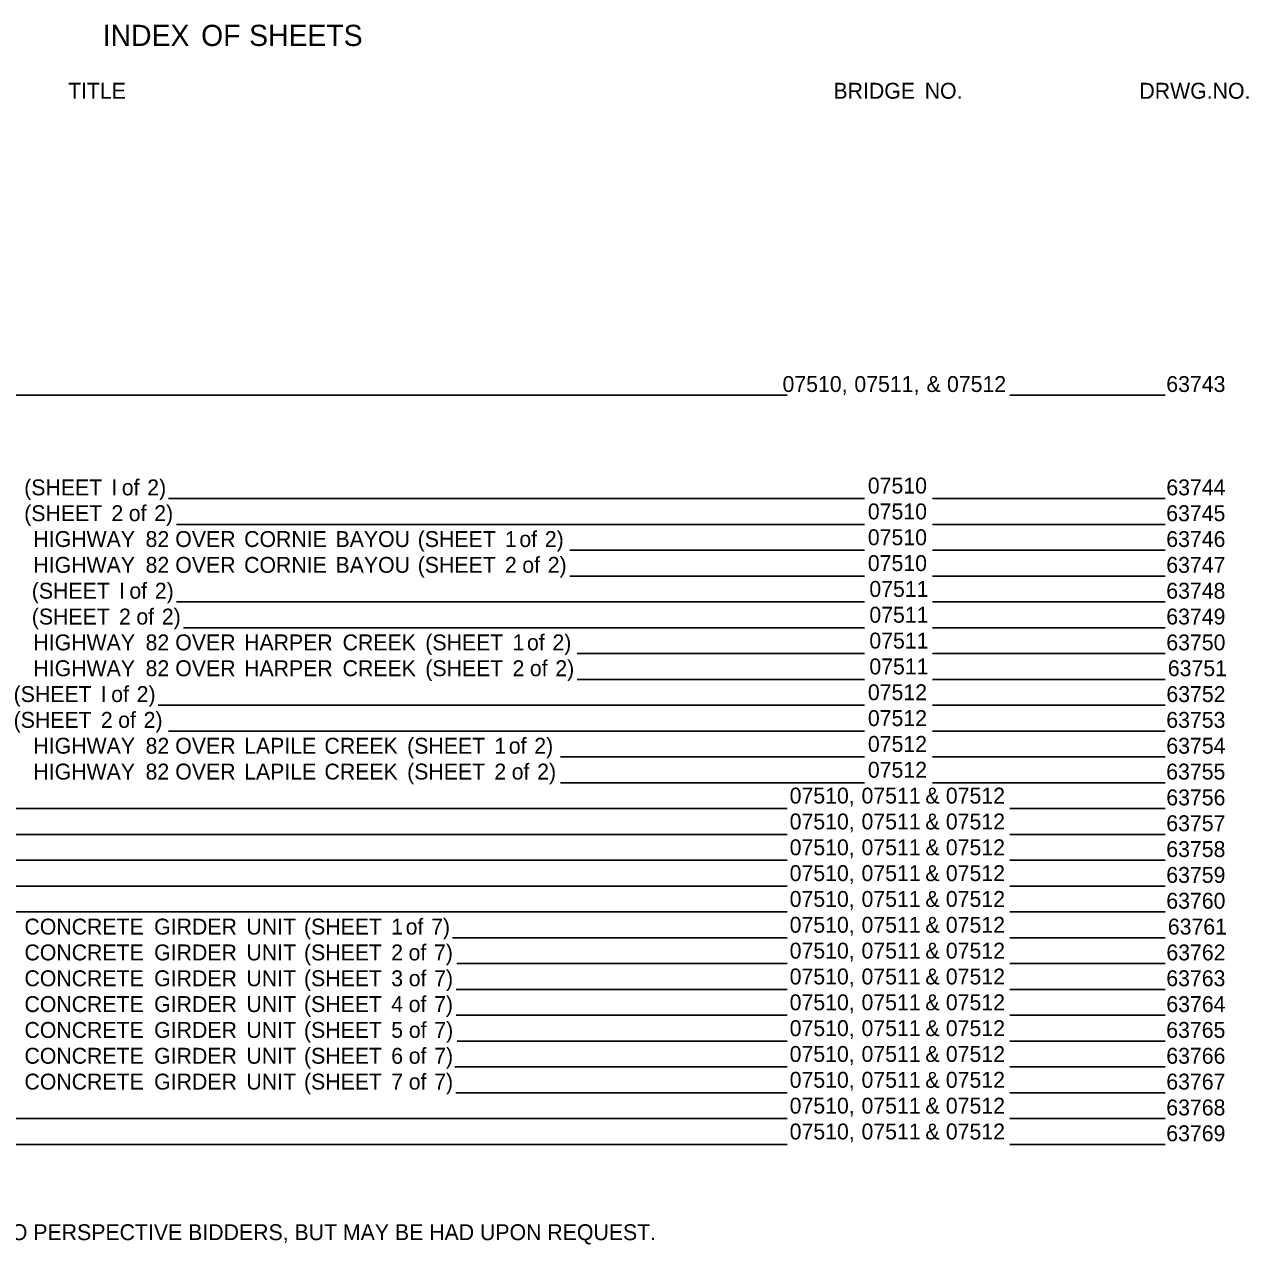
# Model space of a CAD drawing. Extents: x -1392 to 1630, y -1031 to 935.
# Drawn here: x -779 to 144, y -232 to 689 of the extents above; entities that cross this region are included whole.
import ezdxf

# ---------------------------------------------------------------- set-up
doc = ezdxf.new("R2010")
doc.units = 0
doc.layers.add('Default', color=7, linetype='Continuous')

msp = doc.modelspace()

# ---------------------------------------------------------------- linework, layer by layer
at = {"layer": 'Default'}
for p, q in [((-942.93, 409.35), (-203.68, 409.35)), ((-35.54, 409.35), (81.68, 409.35)), ((-670.48, 331.35), (-145.29, 331.35)), ((-93.89, 331.35), (81.68, 331.35)), ((-664.34, 311.85), (-145.29, 311.85)), ((-93.89, 311.85), (81.68, 311.85)), ((-367.54, 292.35), (-145.29, 292.35)), ((-93.89, 292.35), (81.68, 292.35)), ((-367.54, 272.85), (-145.29, 272.85)), ((-93.89, 272.85), (81.68, 272.85)), ((-664.34, 253.35), (-145.29, 253.35)), ((-93.89, 253.35), (81.68, 253.35)), ((-659.12, 233.85), (-145.29, 233.85)), ((-93.89, 233.85), (81.68, 233.85)), ((-362.01, 214.35), (-145.29, 214.35)), ((-93.89, 214.35), (81.68, 214.35)), ((-362.01, 194.85), (-145.29, 194.85)), ((-93.89, 194.85), (81.68, 194.85)), ((-678.15, 175.35), (-145.29, 175.35)), ((-93.89, 175.35), (81.68, 175.35)), ((-670.48, 155.85), (-145.29, 155.85)), ((-93.89, 155.85), (81.68, 155.85)), ((-374.6, 136.35), (-145.29, 136.35)), ((-93.89, 136.35), (81.68, 136.35)), ((-374.6, 116.85), (-145.29, 116.85)), ((-93.89, 116.85), (81.68, 116.85)), ((-923.8, 97.35), (-203.68, 97.35)), ((-35.54, 97.35), (81.68, 97.35)), ((-919.33, 77.85), (-203.68, 77.85)), ((-35.54, 77.85), (81.68, 77.85)), ((-832.91, 58.35), (-203.68, 58.35)), ((-35.54, 58.35), (81.68, 58.35)), ((-829.47, 38.85), (-203.68, 38.85)), ((-35.54, 38.85), (81.68, 38.85)), ((-922.42, 19.35), (-203.68, 19.35)), ((-35.54, 19.35), (81.68, 19.35)), ((-456.03, -0.15), (-203.68, -0.15)), ((-35.54, -0.15), (81.68, -0.15)), ((-452.93, -19.65), (-203.68, -19.65)), ((-35.54, -19.65), (81.68, -19.65)), ((-453.27, -39.15), (-203.68, -39.15)), ((-35.54, -39.15), (81.68, -39.15)), ((-453.27, -58.65), (-203.68, -58.65)), ((-35.54, -58.65), (81.68, -58.65)), ((-452.58, -78.15), (-203.68, -78.15)), ((-35.54, -78.15), (81.68, -78.15)), ((-454.31, -97.65), (-203.68, -97.65)), ((-35.54, -97.65), (81.68, -97.65)), ((-453.62, -117.15), (-203.68, -117.15)), ((-35.54, -117.15), (81.68, -117.15)), ((-871.3, -136.65), (-203.68, -136.65)), ((-35.54, -136.65), (81.68, -136.65)), ((-834.06, -156.15), (-203.68, -156.15)), ((-35.54, -156.15), (81.68, -156.15))]:
    msp.add_line(p, q, dxfattribs=at)

# ---------------------------------------------------------------- texts
for s, height, p in [('INDEX', 16, (-720.06, 672.88)), (' OF', 16, (-651.76, 672.88)), (' SHEETS', 16, (-615.54, 672.88)), ('TITLE', 12, (-746.25, 633.08)), ('BRIDGE', 12, (-168.7, 633.08)), (' NO.', 12, (-104.32, 633.08)), ('DRWG.NO.', 12, (62.17, 633.08)), ('07510,', 12, (-207.12, 411.75)), (' 07511,', 12, (-157.35, 411.75)), (' &', 12, (-102.93, 411.75)), (' 07512', 12, (-87.47, 411.75)), ('63743', 12, (82.45, 411.75)), (' (SHEET', 12, (-783.78, 333.75)), (' I', 12, (-717.98, 333.75)), (' of', 12, (-710.16, 333.75)), (' 2)', 12, (-690.95, 333.75)), ('07510', 12, (-142.75, 335.1)), ('63744', 12, (82.48, 333.75)), (' (SHEET', 12, (-783.78, 314.25)), (' 2', 12, (-717.98, 314.25)), (' of', 12, (-704.89, 314.25)), (' 2)', 12, (-685.67, 314.25)), ('07510', 12, (-142.75, 315.6)), ('63745', 12, (82.4, 314.25)), (' HIGHWAY', 12, (-776.84, 294.75)), (' 82', 12, (-692.2, 294.75)), (' OVER', 12, (-669.79, 294.75)), (' CORNIE', 12, (-617.84, 294.75)), (' BAYOU', 12, (-548.87, 294.75)), (' (SHEET', 12, (-486.86, 294.75)), (' 1', 12, (-421.05, 294.75)), (' of', 12, (-410.16, 294.75)), (' 2)', 12, (-390.94, 294.75)), ('07510', 12, (-142.75, 296.1)), ('63746', 12, (82.45, 294.75)), (' HIGHWAY', 12, (-776.84, 275.25)), (' 82', 12, (-692.2, 275.25)), (' OVER', 12, (-669.79, 275.25)), (' CORNIE', 12, (-617.84, 275.25)), (' BAYOU', 12, (-548.87, 275.25)), (' (SHEET', 12, (-486.86, 275.25)), (' 2', 12, (-421.05, 275.25)), (' of', 12, (-407.96, 275.25)), (' 2)', 12, (-388.74, 275.25)), ('07510', 12, (-142.75, 276.6)), ('63747', 12, (82.45, 275.25)), (' (SHEET', 12, (-778.06, 255.75)), (' of', 12, (-704.44, 255.75)), (' 2)', 12, (-685.22, 255.75)), ('07511', 12, (-141.61, 257.1)), ('63748', 12, (82.44, 255.75)), (' I', 12, (-712.25, 255.75)), ('07511', 12, (-141.61, 237.6)), (' (SHEET', 12, (-778.06, 236.25)), (' 2', 12, (-712.25, 236.25)), (' of', 12, (-699.16, 236.25)), (' 2)', 12, (-679.95, 236.25)), ('63749', 12, (82.44, 236.25)), (' HIGHWAY', 12, (-776.84, 216.75)), (' 82', 12, (-692.2, 216.75)), (' OVER', 12, (-669.79, 216.75)), (' HARPER', 12, (-617.84, 216.75)), (' CREEK', 12, (-543.53, 216.75)), (' (SHEET', 12, (-481.13, 216.75)), (' 1', 12, (-415.32, 216.75)), (' of', 12, (-404.43, 216.75)), (' 2)', 12, (-385.21, 216.75)), ('07511', 12, (-141.61, 218.1)), ('63750', 12, (82.47, 216.75)), (' HIGHWAY', 12, (-776.84, 197.25)), (' 82', 12, (-692.2, 197.25)), (' OVER', 12, (-669.79, 197.25)), (' HARPER', 12, (-617.84, 197.25)), (' CREEK', 12, (-543.53, 197.25)), (' (SHEET', 12, (-481.13, 197.25)), (' 2', 12, (-415.32, 197.25)), (' of', 12, (-402.23, 197.25)), (' 2)', 12, (-383.02, 197.25)), ('07511', 12, (-141.61, 198.6)), ('63751', 12, (83.61, 197.25)), (' (SHEET', 12, (-791.76, 177.75)), (' I', 12, (-725.95, 177.75)), (' of', 12, (-718.14, 177.75)), (' 2)', 12, (-698.92, 177.75)), ('07512', 12, (-142.71, 179.1)), ('63752', 12, (82.51, 177.75)), (' (SHEET', 12, (-791.76, 158.25)), (' 2', 12, (-725.95, 158.25)), (' of', 12, (-712.86, 158.25)), (' 2)', 12, (-693.65, 158.25)), ('07512', 12, (-142.71, 159.6)), ('63753', 12, (82.45, 158.25)), (' HIGHWAY', 12, (-776.84, 138.75)), (' 82', 12, (-692.2, 138.75)), (' OVER', 12, (-669.79, 138.75)), (' LAPILE', 12, (-617.84, 138.75)), (' CREEK', 12, (-557.23, 138.75)), (' (SHEET', 12, (-494.83, 138.75)), (' 1', 12, (-429.02, 138.75)), (' of', 12, (-418.13, 138.75)), (' 2)', 12, (-398.91, 138.75)), ('07512', 12, (-142.71, 140.1)), ('63754', 12, (82.48, 138.75)), (' HIGHWAY', 12, (-776.84, 119.25)), (' 82', 12, (-692.2, 119.25)), (' OVER', 12, (-669.79, 119.25)), (' LAPILE', 12, (-617.84, 119.25)), (' CREEK', 12, (-557.23, 119.25)), (' (SHEET', 12, (-494.83, 119.25)), (' 2', 12, (-429.02, 119.25)), (' of', 12, (-415.94, 119.25)), (' 2)', 12, (-396.72, 119.25)), ('07512', 12, (-142.71, 120.6)), ('63755', 12, (82.4, 119.25)), ('07510,', 12, (-201.74, 101.1)), (' 07511', 12, (-151.97, 101.1)), (' &', 12, (-103.8, 101.1)), (' 07512', 12, (-88.34, 101.1)), ('63756', 12, (82.45, 99.75)), ('07510,', 12, (-201.74, 81.6)), (' 07511', 12, (-151.97, 81.6)), (' &', 12, (-103.8, 81.6)), (' 07512', 12, (-88.34, 81.6)), ('63757', 12, (82.45, 80.25)), ('07510,', 12, (-201.74, 62.1)), (' 07511', 12, (-151.97, 62.1)), (' &', 12, (-103.8, 62.1)), (' 07512', 12, (-88.34, 62.1)), ('63758', 12, (82.44, 60.75)), ('07510,', 12, (-201.74, 42.6)), (' 07511', 12, (-151.97, 42.6)), (' &', 12, (-103.8, 42.6)), (' 07512', 12, (-88.34, 42.6)), ('63759', 12, (82.44, 41.25)), ('07510,', 12, (-201.74, 23.1)), (' 07511', 12, (-151.97, 23.1)), (' &', 12, (-103.8, 23.1)), (' 07512', 12, (-88.34, 23.1)), ('63760', 12, (82.47, 21.75)), (' CONCRETE', 12, (-783.6, 2.25)), (' GIRDER', 12, (-685.74, 2.25)), (' UNIT', 12, (-616.1, 2.25)), (' (SHEET', 12, (-572.67, 2.25)), (' 1', 12, (-506.86, 2.25)), (' of', 12, (-495.97, 2.25)), (' 7)', 12, (-476.75, 2.25)), ('07510,', 12, (-201.74, 3.6)), (' 07511', 12, (-151.97, 3.6)), (' &', 12, (-103.8, 3.6)), (' 07512', 12, (-88.34, 3.6)), ('63761', 12, (83.61, 2.25)), (' CONCRETE', 12, (-783.6, -17.25)), (' GIRDER', 12, (-685.74, -17.25)), (' UNIT', 12, (-616.1, -17.25)), (' (SHEET', 12, (-572.67, -17.25)), (' 2', 12, (-506.86, -17.25)), (' of', 12, (-493.77, -17.25)), (' 7)', 12, (-474.56, -17.25)), ('07510,', 12, (-201.74, -15.9)), (' 07511', 12, (-151.97, -15.9)), (' &', 12, (-103.8, -15.9)), (' 07512', 12, (-88.34, -15.9)), ('63762', 12, (82.51, -17.25)), (' CONCRETE', 12, (-783.6, -36.75)), (' GIRDER', 12, (-685.74, -36.75)), (' UNIT', 12, (-616.1, -36.75)), (' (SHEET', 12, (-572.67, -36.75)), (' 3', 12, (-506.86, -36.75)), (' of', 12, (-493.64, -36.75)), (' 7)', 12, (-474.43, -36.75)), ('07510,', 12, (-201.74, -35.4)), (' 07511', 12, (-151.97, -35.4)), (' &', 12, (-103.8, -35.4)), (' 07512', 12, (-88.34, -35.4)), ('63763', 12, (82.45, -36.75)), (' CONCRETE', 12, (-783.6, -56.25)), (' GIRDER', 12, (-685.74, -56.25)), (' UNIT', 12, (-616.1, -56.25)), (' (SHEET', 12, (-572.67, -56.25)), (' 4', 12, (-506.86, -56.25)), (' of', 12, (-493.7, -56.25)), (' 7)', 12, (-474.48, -56.25)), ('07510,', 12, (-201.74, -54.9)), (' 07511', 12, (-151.97, -54.9)), (' &', 12, (-103.8, -54.9)), (' 07512', 12, (-88.34, -54.9)), ('63764', 12, (82.48, -56.25)), (' CONCRETE', 12, (-783.6, -75.75)), (' GIRDER', 12, (-685.74, -75.75)), (' UNIT', 12, (-616.1, -75.75)), (' (SHEET', 12, (-572.67, -75.75)), (' 5', 12, (-506.86, -75.75)), (' of', 12, (-493.55, -75.75)), (' 7)', 12, (-474.34, -75.75)), ('07510,', 12, (-201.74, -74.4)), (' 07511', 12, (-151.97, -74.4)), (' &', 12, (-103.8, -74.4)), (' 07512', 12, (-88.34, -74.4)), ('63765', 12, (82.4, -75.75)), (' CONCRETE', 12, (-783.6, -95.25)), (' GIRDER', 12, (-685.74, -95.25)), (' (SHEET', 12, (-572.67, -95.25)), (' 6', 12, (-506.86, -95.25)), (' of', 12, (-493.64, -95.25)), (' 7)', 12, (-474.43, -95.25)), ('07510,', 12, (-201.74, -93.9)), (' 07511', 12, (-151.97, -93.9)), (' &', 12, (-103.8, -93.9)), (' 07512', 12, (-88.34, -93.9)), ('63766', 12, (82.45, -95.25)), (' UNIT', 12, (-616.1, -95.25)), ('07510,', 12, (-201.74, -113.4)), (' 07511', 12, (-151.97, -113.4)), (' &', 12, (-103.8, -113.4)), (' 07512', 12, (-88.34, -113.4)), (' CONCRETE', 12, (-783.6, -114.75)), (' GIRDER', 12, (-685.74, -114.75)), (' UNIT', 12, (-616.1, -114.75)), (' (SHEET', 12, (-572.67, -114.75)), (' 7', 12, (-506.86, -114.75)), (' of', 12, (-493.64, -114.75)), (' 7)', 12, (-474.43, -114.75)), ('63767', 12, (82.45, -114.75)), ('07510,', 12, (-201.74, -132.9)), (' 07511', 12, (-151.97, -132.9)), (' &', 12, (-103.8, -132.9)), (' 07512', 12, (-88.34, -132.9)), ('63768', 12, (82.44, -134.25)), ('07510,', 12, (-201.74, -152.4)), (' 07511', 12, (-151.97, -152.4)), (' &', 12, (-103.8, -152.4)), (' 07512', 12, (-88.34, -152.4)), ('63769', 12, (82.44, -153.75)), ('NOTE: CROSS SECTIONS ARE NOT NORMALLY INCLUDED IN PLANS SOLD TO PERSPECTIVE BIDDERS, BUT MAY BE HAD UPON REQUEST.', 12, (-1381.43, -228.41))]:
    msp.add_text(s, height=height, dxfattribs=at).set_placement(p)

doc.saveas('drawing.dxf')
